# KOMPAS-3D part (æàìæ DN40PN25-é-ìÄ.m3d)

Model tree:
1. Объединить компоненты:1  (labels: СЕНС DN40PN25-В-НО)

Referenced files in D:\Савин\!СЕНСОР\3D для заказчика\!Новый перечень\СЕНС\6. СЕНС-В-НО\DN40\: СЕНС DN40PN25-В-НО.a3d
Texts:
  СЕНС DN40PN25-В-НО
  ООО НПП Сенсор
